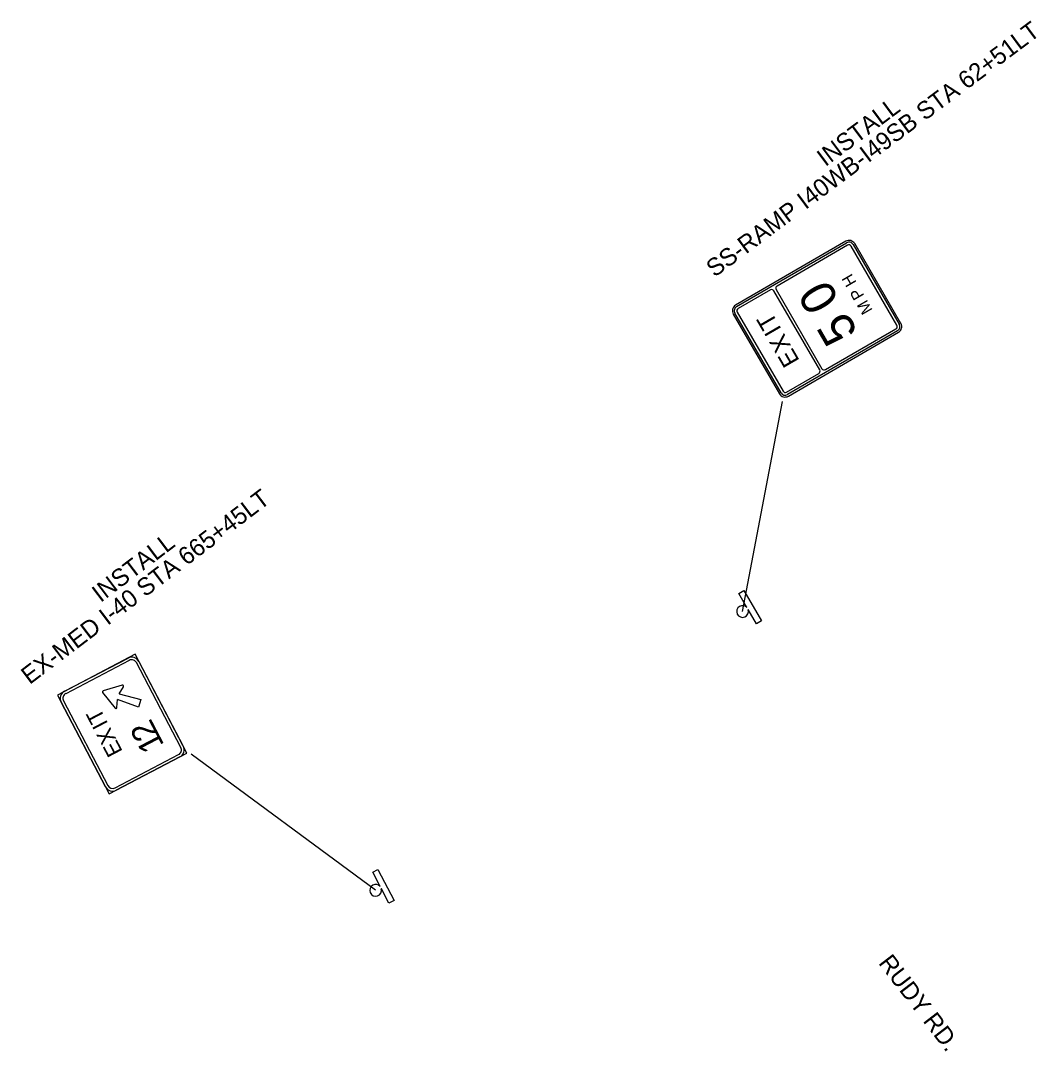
# Model space of a CAD drawing. Extents: x 639753 to 654136, y 407791 to 434220.
# Drawn here: x 646020 to 646715, y 426979 to 427683 of the extents above; entities that cross this region are included whole.
import ezdxf

# ---------------------------------------------------------------- set-up
doc = ezdxf.new("R2010")
doc.units = 0
for name, color, linetype in [('C-TRAF-SYMB', 7, 'Continuous'), ('R_Anno_Text', 7, 'Continuous'), ('R_Dimension', 7, 'Continuous'), ('S_SIGN', 7, 'Continuous')]:
    doc.layers.add(name, color=color, linetype=linetype)

msp = doc.modelspace()

# ---------------------------------------------------------------- linework, layer by layer
at = {"layer": 'C-TRAF-SYMB'}
for p, q in [((646511.16, 427291.75), (646514.61, 427293.77)), ((646516.73, 427282.21), (646511.16, 427291.75)), ((646514.61, 427293.77), (646526.71, 427273.04)), ((646516.63, 427282.15), (646516.73, 427282.21)), ((646517.64, 427280.65), (646517.56, 427280.6)), ((646523.26, 427271.02), (646517.64, 427280.65)), ((646526.71, 427273.04), (646523.26, 427271.02)), ((646260.79, 427101.22), (646264.33, 427103.08)), ((646265.91, 427091.44), (646260.79, 427101.22)), ((646264.33, 427103.08), (646275.46, 427081.81)), ((646265.81, 427091.39), (646265.91, 427091.44)), ((646266.75, 427089.83), (646266.67, 427089.79)), ((646271.92, 427079.96), (646266.75, 427089.83)), ((646275.46, 427081.81), (646271.92, 427079.96))]:
    msp.add_line(p, q, dxfattribs=at)
for centre, start, end in [((646513.76, 427279.37), 44.13685, 120.27473), ((646513.76, 427279.37), 120.27473, 17.95482), ((646262.81, 427088.74), 117.63069, 15.31078), ((646262.81, 427088.74), 41.49281, 117.63069)]:
    msp.add_arc(centre, 4, start, end, dxfattribs=at)
at = {"layer": 'R_Dimension'}
for p, q in [((646513.76, 427279.37), (646541.1, 427423.09)), ((646262.81, 427088.74), (646136.71, 427181.74))]:
    msp.add_line(p, q, dxfattribs=at)
at = {"layer": 'S_SIGN'}
for p, q in [((646584.34, 427532.57), (646509.08, 427488.93)), ((646622.09, 427476.43), (646590.49, 427530.93)), ((646507.44, 427482.78), (646539.04, 427428.28)), ((646545.19, 427426.65), (646620.46, 427470.28))]:
    msp.add_line(p, q, dxfattribs=at)
for points in [[(646584.34, 427532.57), (646509.08, 427488.93)], [(646509.7, 427487.85), (646584.97, 427531.49)], [(646584.34, 427532.57), (646584.34, 427532.57), (646584.34, 427532.57)], [(646589.41, 427530.31), (646621.01, 427475.81)], [(646622.09, 427476.43), (646590.49, 427530.93)], [(646585.63, 427529.85), (646537.4, 427501.89)], [(646619.37, 427475.14), (646588.02, 427529.21)], [(646532.86, 427499.25), (646510.8, 427486.46)], [(646566.6, 427444.55), (646535.25, 427498.62)], [(646536.76, 427499.5), (646568.11, 427445.43)], [(646507.44, 427482.78), (646539.04, 427428.28)], [(646507.44, 427482.78), (646507.44, 427482.78), (646507.44, 427482.78)], [(646540.12, 427428.91), (646508.52, 427483.41)], [(646510.16, 427484.07), (646541.51, 427430)], [(646619.37, 427475.14), (646619.37, 427475.14), (646619.37, 427475.14)], [(646622.09, 427476.43), (646622.09, 427476.43), (646622.09, 427476.43)], [(646619.83, 427471.36), (646544.56, 427427.73)], [(646545.19, 427426.65), (646620.46, 427470.28)], [(646570.5, 427444.79), (646618.73, 427472.75)], [(646543.9, 427429.37), (646565.96, 427442.16)], [(646566.6, 427444.55), (646566.6, 427444.55), (646566.6, 427444.55)], [(646545.19, 427426.65), (646545.19, 427426.65), (646545.19, 427426.65)], [(646133.73, 427182.45), (646098.31, 427250.1), (646045.16, 427222.28), (646080.57, 427154.62), (646133.73, 427182.45), (646133.73, 427182.45), (646133.73, 427182.45)], [(646049.99, 427224.81), (646093.48, 427247.58)], [(646094.32, 427245.96), (646050.83, 427223.2)], [(646094.32, 427245.96), (646094.32, 427245.96), (646094.32, 427245.96)], [(646129.59, 427186.44), (646099.23, 427244.43)], [(646100.84, 427245.27), (646131.2, 427187.28)], [(646089.53, 427228.91), (646076.42, 427225.04)], [(646087.42, 427223.14), (646090.31, 427227.9)], [(646076.08, 427223.96), (646084.65, 427213.3)], [(646076.61, 427224.38), (646076.61, 427224.38), (646076.61, 427224.38)], [(646087.42, 427223.14), (646102.15, 427219.25), (646102.15, 427219.25), (646102.15, 427219.25)], [(646078.04, 427159.46), (646047.69, 427217.45)], [(646049.3, 427218.29), (646079.65, 427160.3)], [(646049.3, 427218.29), (646049.3, 427218.29), (646049.3, 427218.29)], [(646085.87, 427213.68), (646086.19, 427219.24)], [(646102.15, 427219.25), (646100.52, 427214.05), (646086.19, 427219.24)], [(646129.59, 427186.44), (646129.59, 427186.44), (646129.59, 427186.44)], [(646084.56, 427158.76), (646128.05, 427181.53)], [(646128.89, 427179.92), (646085.4, 427157.15)], [(646084.56, 427158.76), (646084.56, 427158.76), (646084.56, 427158.76)]]:
    msp.add_lwpolyline(points, dxfattribs=at)
for centre, radius, start, end in [((646586.6, 427528.68), 4.5, 30.10451, 120.10472), ((646586.6, 427528.68), 4.5, 30.10451, 120.10472), ((646586.6, 427528.68), 3.25, 30.10451, 120.10472), ((646586.51, 427528.34), 1.75, 30.10451, 120.10472), ((646538.28, 427500.37), 1.75, 120.10446, 210.10467), ((646533.74, 427497.74), 1.75, 30.10451, 120.10472), ((646511.33, 427485.04), 4.5, 120.10446, 210.10467), ((646511.33, 427485.04), 4.5, 120.10446, 210.10467), ((646511.33, 427485.04), 3.25, 120.10446, 210.10467), ((646511.68, 427484.95), 1.75, 120.10446, 210.10467), ((646617.86, 427474.27), 1.75, 300.1043, 30.10451), ((646618.2, 427474.18), 3.25, 300.1043, 30.10451), ((646618.2, 427474.18), 4.5, 300.1043, 30.10451), ((646618.2, 427474.18), 4.5, 300.1043, 30.10451), ((646569.63, 427446.3), 1.75, 210.10467, 300.1043), ((646565.08, 427443.67), 1.75, 300.1043, 30.10451), ((646542.93, 427430.54), 4.5, 210.10467, 300.1043), ((646542.93, 427430.54), 4.5, 210.10467, 300.1043), ((646542.93, 427430.54), 3.25, 210.10467, 300.1043), ((646543.02, 427430.88), 1.75, 210.10467, 300.1043), ((646096.01, 427242.74), 5.45, 27.629, 117.62921), ((646096.01, 427242.74), 3.64, 27.629, 117.62921), ((646089.73, 427228.26), 0.682, 328.66706, 106.4508), ((646052.52, 427219.98), 5.45, 117.62894, 207.62915), ((646052.52, 427219.98), 3.64, 117.62894, 207.62915), ((646076.61, 427224.38), 0.682, 106.4508, 218.80668), ((646085.18, 427213.72), 0.682, 218.80698, 356.5913), ((646126.37, 427184.75), 3.64, 297.62879, 27.629), ((646126.37, 427184.75), 5.45, 297.62879, 27.629), ((646082.87, 427161.99), 5.45, 207.62915, 297.62879), ((646082.87, 427161.99), 3.64, 207.62915, 297.62879)]:
    msp.add_arc(centre, radius, start, end, dxfattribs=at)

# ---------------------------------------------------------------- texts
at = {"layer": 'R_Anno_Text'}
for s, rotation, p in [('SS-RAMP I40WB-I49SB STA 62+51LT', 36.69024, (646494.64, 427507.5)), ('INSTALL', 36.69024, (646570.42, 427583.18)), ('EX-MED I-40 STA 665+45LT', 37.12523, (646026.14, 427229.11)), ('INSTALL', 37.12523, (646074.62, 427285.14)), ('RUDY RD.', 307.53429, (646606.33, 427038.95))]:
    msp.add_text(s, height=12, rotation=rotation, dxfattribs=at).set_placement(p)
at = {"layer": 'S_SIGN'}
for s, height, rotation, p in [('H', 8, 120.10446, (646592.02, 427504.37)), ('0', 24, 120.10446, (646580.52, 427492.32)), ('P', 8, 120.10446, (646597.26, 427495.34)), ('M', 8, 120.10446, (646603, 427485.44)), ('T', 12, 120.10446, (646538.24, 427476.51)), ('5', 24, 120.10446, (646593.21, 427470.42)), ('I', 12, 120.10446, (646540.68, 427472.31)), ('X', 12, 120.10446, (646547.25, 427460.98)), ('E', 12, 120.10446, (646553.07, 427450.94)), ('T', 10.91, 117.62894, (646078.15, 427206.3)), ('2', 16.36, 117.62894, (646114.3, 427196.04)), ('I', 10.91, 117.62894, (646080.07, 427202.63)), ('X', 10.91, 117.62894, (646085.53, 427192.19)), ('E', 10.91, 117.62894, (646089.98, 427183.69)), ('1', 16.36, 117.62894, (646118.48, 427188.06))]:
    msp.add_text(s, height=height, rotation=rotation, dxfattribs=at).set_placement(p)

doc.saveas('drawing.dxf')
